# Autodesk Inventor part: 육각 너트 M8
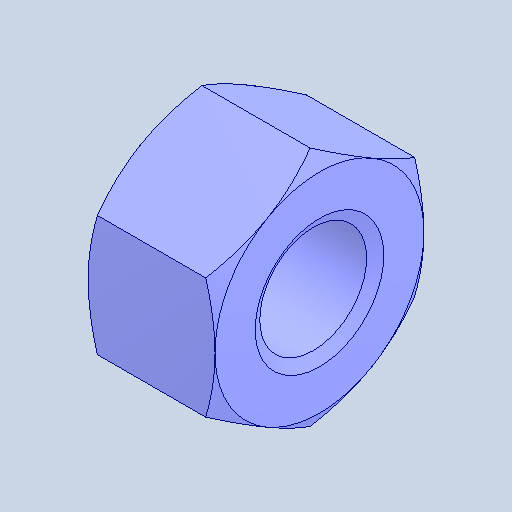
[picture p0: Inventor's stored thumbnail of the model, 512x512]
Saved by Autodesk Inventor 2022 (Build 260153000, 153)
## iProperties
Created: 2024-11
Part Number: 육각 너트 M8
Material: 강철, 연강
Description: 6각 너트 및 6각 가는 너트
Document SubType Name: Modeling
Designer: PC-12
Density: 7.85 g/cm^3
Appearance: 기본값
Author: jhkim
Sending System: Autodesk Inventor 2025
Preprocessor: ST-DEVELOPER v20
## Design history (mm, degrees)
node "육각 너트 M81"
node "솔리드1"
body "Solid1"
